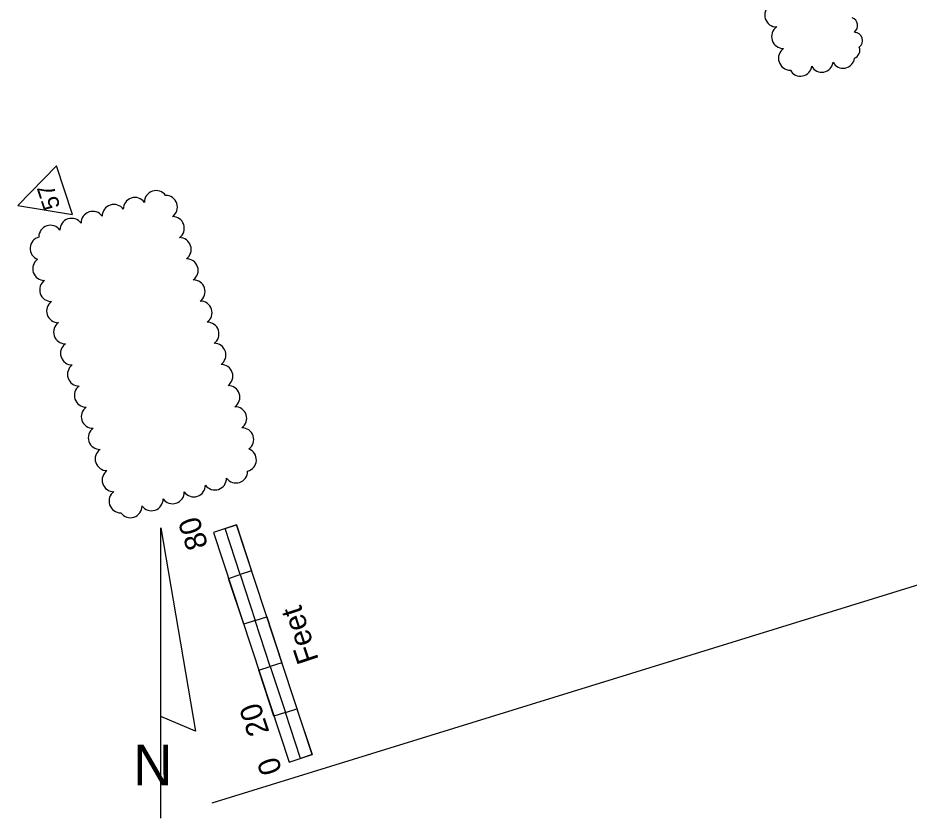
# Model space of a CAD drawing. Extents: x 929207 to 930387, y 631822 to 633132.
# Drawn here: x 929502.4 to 929797.2, y 631822 to 632086.7 of the extents above; entities that cross this region are included whole.
import ezdxf

# ---------------------------------------------------------------- set-up
doc = ezdxf.new("R2010")
doc.units = 0
for name, color, linetype in [('PoleLight', 7, 'Continuous'), ('PullBox', 7, 'Continuous'), ('TextMinor', 7, 'Continuous'), ('TextMisc', 7, 'Continuous')]:
    doc.layers.add(name, color=color, linetype=linetype)

msp = doc.modelspace()

# ---------------------------------------------------------------- linework, layer by layer
at = {"layer": 'PoleLight'}
msp.add_lwpolyline([(929502.36, 632024.65), (929520.46, 632021.7), (929515.18, 632037.76)], close=True, dxfattribs=at)
for centre, radius, start, end in [((929753.38, 632087.64), 3.93, 125.154, 270.154), ((929777.54, 632084.19), 2.66, 305.6866, 72.1812), ((929755.66, 632080.49), 3.93, 125.154, 270.154), ((929779.17, 632079.23), 2.66, 305.6866, 90.6866), ((929757.93, 632073.35), 3.93, 125.154, 270.154), ((929778.08, 632076.02), 2.84, 291.0685, 21.599), ((929768.31, 632072.5), 3.76, 208.0558, 353.0558), ((929775.37, 632073.82), 3.76, 208.0558, 353.0558), ((929761.26, 632071.19), 3.76, 208.0558, 353.0558), ((929541.11, 632023.44), 3.86, 35.6866, 180.6866), ((929548.1, 632025.74), 3.86, 35.6866, 180.6866), ((929551.27, 632024.13), 3.86, 305.6866, 90.6866), ((929534.12, 632021.15), 3.86, 35.6866, 180.6866), ((929527.13, 632018.85), 3.86, 35.6866, 180.6866), ((929520.14, 632016.55), 3.86, 35.6866, 180.6866), ((929553.57, 632017.14), 3.86, 305.6866, 90.6866), ((929513.15, 632014.26), 3.86, 35.6866, 180.6866), ((929510.26, 632010.48), 3.85, 104.4101, 249.4101), ((929555.87, 632010.16), 3.86, 305.6866, 90.6866), ((929511.15, 632003.74), 3.86, 125.6866, 270.6866), ((929558.16, 632003.17), 3.86, 305.6866, 90.6866), ((929513.45, 631996.75), 3.86, 125.6866, 270.6866), ((929560.46, 631996.18), 3.86, 305.6866, 90.6866), ((929515.74, 631989.76), 3.86, 125.6866, 270.6866), ((929562.75, 631989.19), 3.86, 305.6866, 90.6866), ((929565.05, 631982.2), 3.86, 305.6866, 90.6866), ((929518.04, 631982.77), 3.86, 125.6866, 270.6866), ((929520.33, 631975.79), 3.86, 125.6866, 270.6866), ((929567.34, 631975.21), 3.86, 305.6866, 90.6866), ((929522.63, 631968.8), 3.86, 125.6866, 270.6866), ((929569.64, 631968.22), 3.86, 305.6866, 90.6866), ((929524.93, 631961.81), 3.86, 125.6866, 270.6866), ((929571.94, 631961.24), 3.86, 305.6866, 90.6866), ((929527.22, 631954.82), 3.86, 125.6866, 270.6866), ((929574.23, 631954.25), 3.86, 305.6866, 90.6866), ((929529.52, 631947.83), 3.86, 125.6866, 270.6866), ((929576.53, 631947.26), 3.86, 305.6866, 90.6866), ((929531.81, 631940.84), 3.86, 125.6866, 270.6866), ((929577.42, 631940.52), 3.85, 284.4101, 69.4101), ((929534.11, 631933.85), 3.86, 125.6866, 270.6866), ((929574.53, 631936.74), 3.86, 215.6866, 0.6866), ((929567.54, 631934.44), 3.86, 215.6866, 0.6866), ((929536.4, 631926.87), 3.86, 125.6866, 270.6866), ((929560.55, 631932.15), 3.86, 215.6866, 0.6866), ((929546.57, 631927.56), 3.86, 215.6866, 0.6866), ((929553.56, 631929.85), 3.86, 215.6866, 0.6866), ((929539.58, 631925.26), 3.86, 215.6866, 0.6866)]:
    msp.add_arc(centre, radius, start, end, dxfattribs=at)
at = {"layer": 'PullBox'}
for p, q in [((929574.71, 631919.02), (929567.11, 631916.52)), ((929599.68, 631843.02), (929574.71, 631919.02)), ((929567.11, 631916.52), (929592.08, 631840.52)), ((929592.08, 631840.52), (929599.68, 631843.02))]:
    msp.add_line(p, q, dxfattribs=at)
for points in [[(929579.7, 631903.82), (929575.9, 631902.57), (929570.91, 631917.77), (929574.71, 631919.02)], [(929580.9, 631887.37), (929577.09, 631886.12), (929572.1, 631901.32), (929575.9, 631902.57)], [(929589.69, 631873.42), (929585.89, 631872.17), (929580.9, 631887.37), (929584.7, 631888.62)], [(929590.88, 631856.97), (929587.08, 631855.72), (929582.09, 631870.92), (929585.89, 631872.17)], [(929599.68, 631843.02), (929595.88, 631841.77), (929590.88, 631856.97), (929594.68, 631858.22)]]:
    msp.add_lwpolyline(points, close=True, dxfattribs=at)
at = {"layer": 'TextMinor'}
msp.add_lwpolyline([(930254.51, 632039.52), (929910.55, 631933.25), (929566.59, 631826.98)], dxfattribs=at)
at = {"layer": 'TextMisc'}
msp.add_line((929549.64, 631822), (929549.64, 631918), dxfattribs=at)
msp.add_lwpolyline([(929549.64, 631855.6), (929549.64, 631918), (929561.16, 631850.8)], close=True, dxfattribs=at)

# ---------------------------------------------------------------- texts
at = {"layer": 'PoleLight'}
msp.add_text('57', height=5.6, rotation=108.1866, dxfattribs=at).set_placement((929516.47, 632024.31))
at = {"layer": 'PullBox'}
for s, p in [('80', (929565.4, 631912.12)), ('Feet', (929601.98, 631874.45)), ('20', (929585.64, 631850.51)), ('0', (929589.85, 631837.7))]:
    msp.add_text(s, height=7.2, rotation=108.1866, dxfattribs=at).set_placement(p)
at = {"layer": 'TextMisc'}
msp.add_text('N', height=13.43, dxfattribs=at).set_placement((929540.52, 631832.87))

doc.saveas('drawing.dxf')
